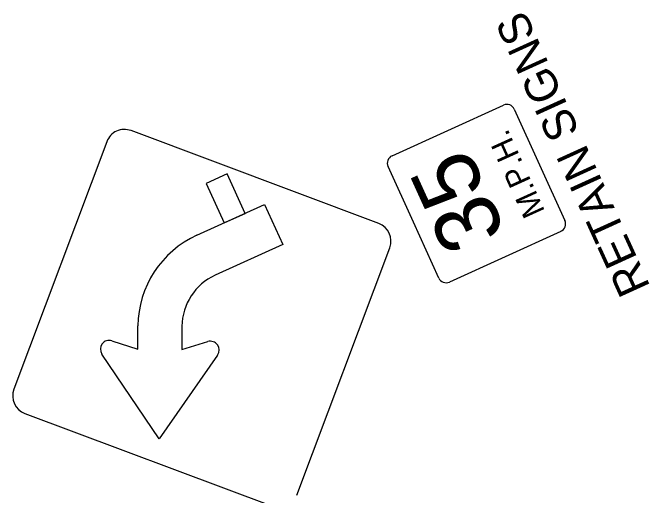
# Model space of a CAD drawing. Extents: x 2096999 to 2102576, y 682920 to 687015.
# Drawn here: x 2101941.7 to 2102079.4, y 683124.6 to 683229.1 of the extents above; entities that cross this region are included whole.
import ezdxf

# ---------------------------------------------------------------- set-up
doc = ezdxf.new("R2010")
doc.units = 0
doc.layers.add('Default', color=7, linetype='Continuous')

msp = doc.modelspace()

# ---------------------------------------------------------------- linework, layer by layer
at = {"layer": 'Default'}
for p, q in [((2102023.77, 683198.1), (2102047.89, 683209.07)), ((2102020.88, 683183.48), (2101967.3, 683203.56)), ((2101962.04, 683201.17), (2101941.96, 683147.59)), ((2101987.46, 683183.61), (2101991.98, 683185.66)), ((2102000.11, 683178.9), (2101985.5, 683172.26)), ((2102000.11, 683178.9), (2101985.5, 683172.26)), ((2102000.11, 683178.9), (2101985.5, 683172.26)), ((2102003.19, 683124.64), (2102023.27, 683178.23)), ((2101944.35, 683142.33), (2101997.94, 683122.25))]:
    msp.add_line(p, q, dxfattribs=at)
for points in [[(2102050.21, 683208.2), (2102055.69, 683196.14)], [(2102028.38, 683183.72), (2102022.9, 683195.78)], [(2102055.69, 683196.14), (2102061.18, 683184.08)], [(2101991.98, 683185.66), (2101988.1, 683194.18), (2101983.59, 683192.13), (2101987.46, 683183.61)], [(2101981.55, 683180.93), (2101996.17, 683187.57), (2102000.11, 683178.9)], [(2101981.55, 683180.93), (2101996.17, 683187.57), (2102000.11, 683178.9)], [(2101981.55, 683180.93), (2101996.17, 683187.57), (2102000.11, 683178.9)], [(2102033.87, 683171.66), (2102028.38, 683183.72)], [(2102060.31, 683181.76), (2102036.19, 683170.79)], [(2101963.16, 683158.08), (2101968.76, 683156.25), (2101968.8, 683161.29)], [(2101963.16, 683158.08), (2101968.76, 683156.25), (2101968.8, 683161.29)], [(2101963.16, 683158.08), (2101968.76, 683156.25), (2101968.8, 683161.29)], [(2101978.32, 683161.21), (2101978.28, 683156.17), (2101983.91, 683157.9)], [(2101978.32, 683161.21), (2101978.28, 683156.17), (2101983.91, 683157.9)], [(2101978.32, 683161.21), (2101978.28, 683156.17), (2101983.91, 683157.9)], [(2101986.03, 683154.99), (2101973.35, 683136.84), (2101960.98, 683155.2)], [(2101986.03, 683154.99), (2101973.35, 683136.84), (2101960.98, 683155.2)], [(2101986.03, 683154.99), (2101973.35, 683136.84), (2101960.98, 683155.2)]]:
    msp.add_lwpolyline(points, dxfattribs=at)
for centre, radius, start, end in [((2102048.61, 683207.48), 1.75, 24.458, 114.458), ((2101965.86, 683199.74), 4.08, 69.458, 159.458), ((2102024.49, 683196.51), 1.75, 114.458, 204.458), ((2102059.58, 683183.36), 1.75, 294.458, 24.458), ((2102019.45, 683179.66), 4.08, 339.458, 69.458), ((2102035.46, 683172.39), 1.75, 204.445, 294.458), ((2101945.78, 683146.15), 4.08, 159.458, 249.458)]:
    msp.add_arc(centre, radius, start, end, dxfattribs=at)
for centre, major_axis, start_param, end_param in [((2101990.56, 683161.11), (-19.82, -9.01), 4.712389, 5.847944), ((2101990.56, 683161.11), (-19.82, -9.01), 4.712389, 5.847944), ((2101990.56, 683161.11), (-19.82, -9.01), 4.712389, 5.847944), ((2101990.56, 683161.11), (-11.15, -5.07), 4.712389, 5.847944), ((2101990.56, 683161.11), (-11.15, -5.07), 4.712389, 5.847944), ((2101990.56, 683161.11), (-11.15, -5.07), 4.712389, 5.847944), ((2101962.56, 683156.27), (-1.73, -0.79), 3.969953, 6.449197), ((2101962.56, 683156.27), (-1.73, -0.79), 3.969953, 6.449197), ((2101962.56, 683156.27), (-1.73, -0.79), 3.969953, 6.449197), ((2101984.47, 683156.08), (1.73, 0.79), 5.246691, 7.725935), ((2101984.47, 683156.08), (1.73, 0.79), 5.246691, 7.725935), ((2101984.47, 683156.08), (1.73, 0.79), 5.246691, 7.725935)]:
    msp.add_ellipse(centre, major_axis=major_axis, ratio=0.999989, start_param=start_param, end_param=end_param, dxfattribs=at)

# ---------------------------------------------------------------- texts
for s, height, rotation, p in [('RETAIN SIGNS', 7, 114.4888, (2102079.74, 683169.76)), ('M.P.H.', 4.86, 114.458, (2102056.92, 683186.1)), ('35', 14, 114.458, (2102048.56, 683181.47))]:
    msp.add_text(s, height=height, rotation=rotation, dxfattribs=at).set_placement(p)

doc.saveas('drawing.dxf')
